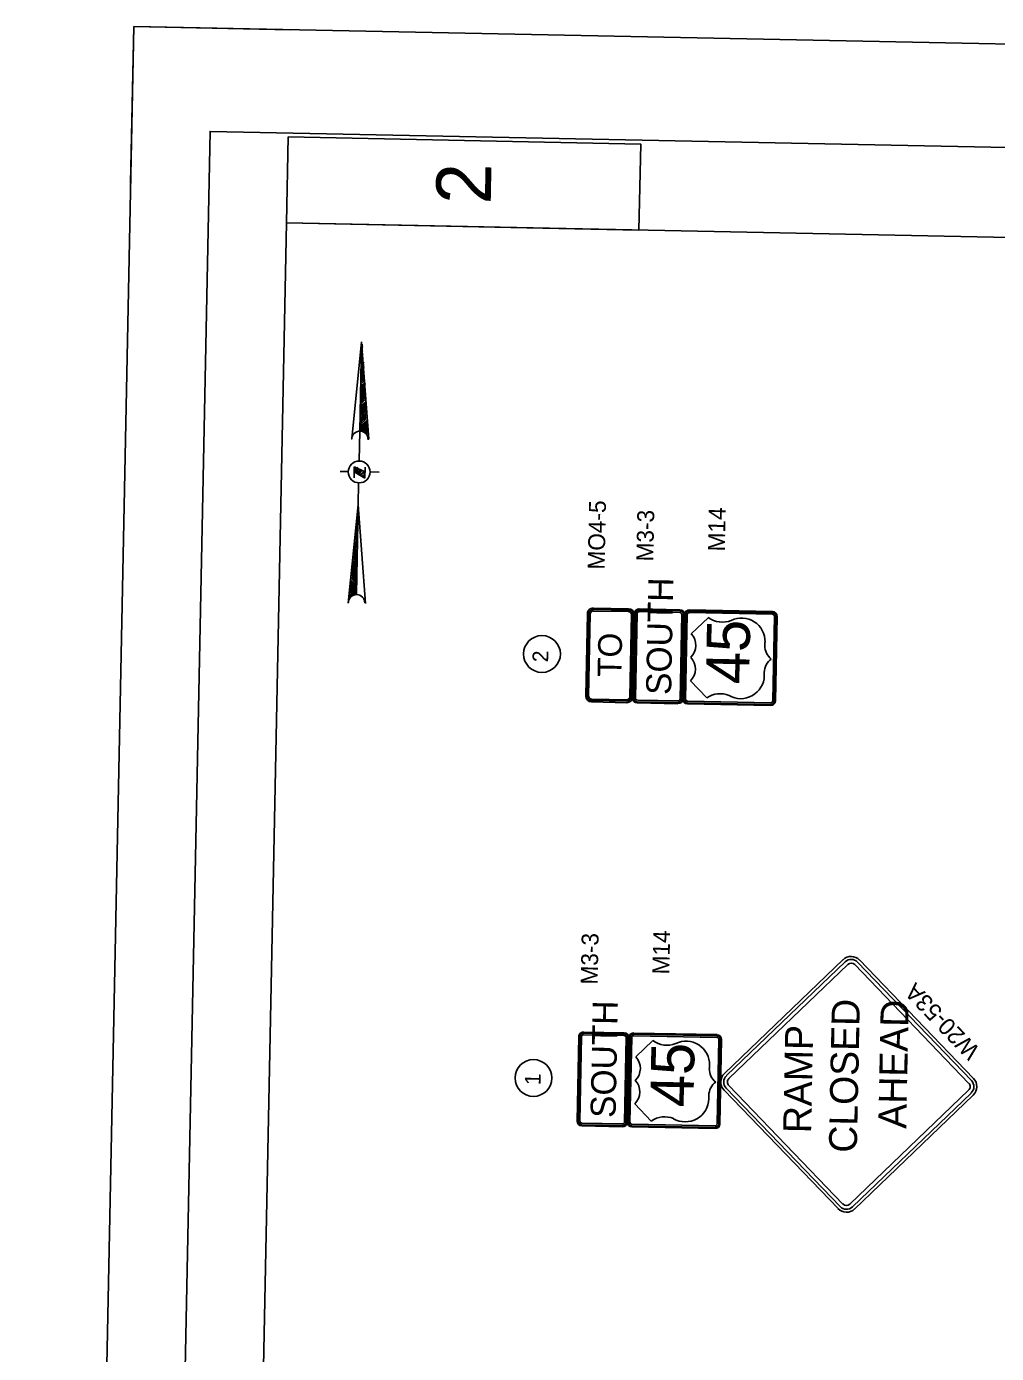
# Model space of a CAD drawing. Extents: x 327762 to 372975, y 127949 to 220470.
# Drawn here: x 344626 to 352364, y 209877 to 220470 of the extents above; entities that cross this region are included whole.
import ezdxf

# ---------------------------------------------------------------- set-up
doc = ezdxf.new("R2010")
doc.units = 0
for name, color, linetype in [('CA-TBLK', 7, 'Continuous'), ('CA-TEXT', 7, 'Continuous'), ('GSBWFILL', 7, 'Continuous'), ('P_SGN_Cell', 7, 'Continuous'), ('PLT_Sheet_Border', 7, 'Continuous'), ('PLT_Sheet_Info', 7, 'Continuous')]:
    doc.layers.add(name, color=color, linetype=linetype)

msp = doc.modelspace()

# ---------------------------------------------------------------- linework, layer by layer
at = {"layer": 'CA-TBLK'}
for p, q in [((347220, 217179), (347298, 217953)), ((347284, 217240), (347298, 217953)), ((347297, 217928), (347310, 217928)), ((347310, 217928), (347297, 217928)), ((347310, 217915), (347297, 217903)), ((347297, 217915), (347310, 217915)), ((347297, 217903), (347309, 217903)), ((347357, 217176), (347298, 217953)), ((347298, 217953), (347298, 217953)), ((347298, 217953), (347298, 217953)), ((347298, 217940), (347298, 217940)), ((347308, 217840), (347295, 217828)), ((347308, 217828), (347295, 217815)), ((347295, 217815), (347308, 217828)), ((347295, 217803), (347308, 217815)), ((347295, 217790), (347307, 217803)), ((347307, 217803), (347295, 217790)), ((347296, 217878), (347309, 217890)), ((347296, 217865), (347309, 217878)), ((347309, 217878), (347296, 217878)), ((347309, 217865), (347296, 217853)), ((347308, 217853), (347296, 217840)), ((347296, 217853), (347308, 217853)), ((347296, 217840), (347308, 217840)), ((347309, 217890), (347297, 217890)), ((347318, 217702), (347292, 217678)), ((347292, 217665), (347318, 217690)), ((347319, 217752), (347293, 217728)), ((347293, 217715), (347319, 217740)), ((347293, 217703), (347318, 217727)), ((347318, 217727), (347293, 217715)), ((347318, 217715), (347293, 217703)), ((347293, 217690), (347318, 217715)), ((347307, 217790), (347294, 217778)), ((347294, 217765), (347320, 217790)), ((347319, 217777), (347294, 217765)), ((347294, 217753), (347319, 217765)), ((347319, 217765), (347294, 217740)), ((347294, 217740), (347319, 217752)), ((347290, 217565), (347328, 217602)), ((347328, 217602), (347290, 217578)), ((347290, 217553), (347328, 217590)), ((347328, 217590), (347290, 217565)), ((347317, 217652), (347291, 217628)), ((347317, 217640), (347291, 217615)), ((347291, 217615), (347317, 217640)), ((347329, 217627), (347291, 217590)), ((347291, 217603), (347329, 217627)), ((347291, 217590), (347329, 217615)), ((347292, 217653), (347317, 217677)), ((347317, 217677), (347292, 217665)), ((347317, 217665), (347292, 217640)), ((347292, 217640), (347317, 217665)), ((347288, 217478), (347327, 217515)), ((347327, 217515), (347288, 217478)), ((347326, 217502), (347288, 217465)), ((347326, 217490), (347288, 217453)), ((347288, 217453), (347326, 217490)), ((347328, 217565), (347289, 217528)), ((347327, 217552), (347289, 217515)), ((347289, 217528), (347327, 217552)), ((347289, 217503), (347327, 217540)), ((347289, 217490), (347327, 217527)), ((347327, 217527), (347289, 217503)), ((347328, 217577), (347290, 217553)), ((347290, 217540), (347328, 217565)), ((347285, 217328), (347336, 217377)), ((347337, 217414), (347286, 217365)), ((347286, 217378), (347337, 217414)), ((347337, 217402), (347286, 217353)), ((347286, 217365), (347337, 217402)), ((347286, 217340), (347337, 217389)), ((347336, 217377), (347286, 217340)), ((347338, 217477), (347287, 217428)), ((347287, 217428), (347338, 217464)), ((347287, 217415), (347338, 217452)), ((347338, 217452), (347287, 217415)), ((347287, 217390), (347338, 217439)), ((347338, 217439), (347287, 217403)), ((347337, 217427), (347287, 217390)), ((347288, 217440), (347338, 217477)), ((347348, 217327), (347284, 217265)), ((347284, 217278), (347348, 217327)), ((347284, 217265), (347348, 217314)), ((347284, 217253), (347347, 217302)), ((347347, 217302), (347284, 217253)), ((347347, 217289), (347284, 217240)), ((347285, 217315), (347336, 217364)), ((347336, 217364), (347285, 217315)), ((347336, 217352), (347285, 217303)), ((347336, 217339), (347285, 217290)), ((347285, 217290), (347336, 217339)), ((347296, 217240), (347347, 217289)), ((347347, 217277), (347309, 217240)), ((347284, 217240), (347279, 217003)), ((347309, 217240), (347347, 217264)), ((347347, 217264), (347321, 217227)), ((347346, 217252), (347321, 217227)), ((347321, 217227), (347346, 217252)), ((347333, 217227), (347346, 217239)), ((347346, 217227), (347333, 217214)), ((347333, 217214), (347346, 217227)), ((347345, 217202), (347346, 217214)), ((347345, 217202), (347345, 217202)), ((347345, 217189), (347345, 217189)), ((347345, 217189), (347345, 217189)), ((347345, 217177), (347357, 217176)), ((347346, 217214), (347346, 217214)), ((347240, 216954), (347239, 216866)), ((347240, 216941), (347253, 216954)), ((347253, 216954), (347240, 216941)), ((347240, 216954), (347240, 216954)), ((347327, 216915), (347240, 216954)), ((347265, 216953), (347240, 216929)), ((347328, 216952), (347326, 216865)), ((347190, 216917), (347127, 216919)), ((347240, 216916), (347278, 216941)), ((347265, 216941), (347240, 216916)), ((347240, 216916), (347265, 216941)), ((347240, 216916), (347326, 216865)), ((347278, 216941), (347252, 216904)), ((347252, 216904), (347290, 216928)), ((347264, 216903), (347302, 216928)), ((347290, 216928), (347264, 216903)), ((347276, 216891), (347302, 216928)), ((347302, 216928), (347277, 216903)), ((347327, 216915), (347289, 216890)), ((347289, 216890), (347314, 216915)), ((347314, 216915), (347289, 216890)), ((347301, 216878), (347327, 216902)), ((347327, 216902), (347301, 216878)), ((347314, 216877), (347326, 216890)), ((347326, 216890), (347314, 216877)), ((347326, 216865), (347326, 216877)), ((347364, 216914), (347439, 216912)), ((347275, 216828), (347272, 216653)), ((347193, 215867), (347272, 216653)), ((347257, 215941), (347272, 216653)), ((347271, 216641), (347271, 216641)), ((347271, 216641), (347271, 216641)), ((347331, 215864), (347272, 216653)), ((347272, 216653), (347272, 216653)), ((347269, 216541), (347270, 216553)), ((347269, 216528), (347269, 216541)), ((347269, 216541), (347269, 216541)), ((347269, 216528), (347269, 216516)), ((347269, 216516), (347269, 216528)), ((347270, 216591), (347271, 216603)), ((347270, 216591), (347270, 216591)), ((347270, 216578), (347270, 216578)), ((347270, 216578), (347270, 216566)), ((347270, 216566), (347270, 216553)), ((347270, 216566), (347270, 216566)), ((347271, 216628), (347271, 216628)), ((347271, 216616), (347271, 216616)), ((347271, 216616), (347271, 216616)), ((347271, 216603), (347271, 216603)), ((347268, 216453), (347255, 216466)), ((347255, 216466), (347268, 216453)), ((347267, 216428), (347255, 216453)), ((347255, 216453), (347267, 216441)), ((347255, 216441), (347267, 216428)), ((347255, 216428), (347267, 216403)), ((347267, 216416), (347255, 216428)), ((347256, 216516), (347269, 216503)), ((347269, 216503), (347256, 216503)), ((347256, 216503), (347268, 216491)), ((347256, 216491), (347268, 216466)), ((347268, 216478), (347256, 216491)), ((347268, 216466), (347256, 216478)), ((347240, 216341), (347265, 216316)), ((347265, 216316), (347240, 216341)), ((347265, 216303), (347240, 216329)), ((347264, 216291), (347240, 216316)), ((347240, 216316), (347264, 216291)), ((347241, 216366), (347265, 216341)), ((347241, 216354), (347265, 216328)), ((347265, 216341), (347241, 216354)), ((347254, 216416), (347266, 216391)), ((347267, 216403), (347254, 216416)), ((347254, 216403), (347266, 216378)), ((347266, 216378), (347254, 216403)), ((347266, 216366), (347254, 216391)), ((347266, 216353), (347254, 216378)), ((347254, 216378), (347266, 216353)), ((347225, 216216), (347262, 216178)), ((347262, 216191), (347226, 216229)), ((347263, 216203), (347238, 216241)), ((347238, 216241), (347263, 216216)), ((347238, 216229), (347262, 216191)), ((347239, 216291), (347264, 216266)), ((347239, 216279), (347263, 216241)), ((347264, 216253), (347239, 216279)), ((347263, 216241), (347239, 216266)), ((347239, 216266), (347263, 216228)), ((347263, 216216), (347239, 216254)), ((347264, 216266), (347240, 216304)), ((347240, 216304), (347264, 216278)), ((347223, 216117), (347260, 216066)), ((347260, 216078), (347223, 216117)), ((347260, 216053), (347223, 216104)), ((347224, 216167), (347261, 216128)), ((347261, 216128), (347224, 216167)), ((347261, 216103), (347224, 216154)), ((347224, 216154), (347261, 216116)), ((347224, 216142), (347261, 216103)), ((347224, 216129), (347260, 216078)), ((347260, 216091), (347224, 216129)), ((347225, 216204), (347262, 216166)), ((347262, 216166), (347225, 216204)), ((347225, 216192), (347262, 216153)), ((347262, 216153), (347225, 216192)), ((347261, 216141), (347225, 216179)), ((347209, 216042), (347258, 215978)), ((347258, 215991), (347209, 216042)), ((347258, 215978), (347209, 216029)), ((347258, 215966), (347209, 216017)), ((347209, 216017), (347258, 215966)), ((347257, 215941), (347209, 216004)), ((347209, 216004), (347258, 215953)), ((347210, 216054), (347259, 216003)), ((347259, 216003), (347210, 216054)), ((347222, 216067), (347259, 216016)), ((347259, 216041), (347223, 216092)), ((347223, 216092), (347260, 216053)), ((347259, 216028), (347223, 216079)), ((347223, 216079), (347259, 216028)), ((347194, 215917), (347207, 215904)), ((347194, 215905), (347207, 215904)), ((347207, 215904), (347194, 215905)), ((347194, 215892), (347194, 215892)), ((347194, 215892), (347194, 215892)), ((347219, 215917), (347207, 215942)), ((347207, 215942), (347220, 215929)), ((347207, 215929), (347219, 215917)), ((347207, 215917), (347207, 215929)), ((347208, 215992), (347257, 215941)), ((347208, 215979), (347245, 215941)), ((347257, 215941), (347208, 215979)), ((347208, 215967), (347232, 215929)), ((347245, 215929), (347208, 215967)), ((347232, 215929), (347208, 215954)), ((347194, 215880), (347194, 215880))]:
    msp.add_line(p, q, dxfattribs=at)
msp.add_circle((347280, 216914), 87, dxfattribs=at)
for centre, start, end in [((347285, 217175), 358.8468, 178.8468), ((347285, 217175), 178.84682431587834, 178.8468298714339), ((347259, 215870), 358.8468, 178.8468), ((347259, 215870), 358.84700764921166, 358.8470132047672)]:
    msp.add_arc(centre, 65.2, start, end, dxfattribs=at)
at = {"layer": 'CA-TEXT'}
for centre in [(348738, 215461), (348670, 212076)]:
    msp.add_circle(centre, 147, dxfattribs=at)
at = {"layer": 'GSBWFILL'}
msp.add_lwpolyline([(344626, 177980), (345482, 220470), (372975, 219916), (372119, 177427)], close=True, dxfattribs=at)
at = {"layer": 'P_SGN_Cell'}
for p, q in [((349462, 215109), (349475, 215784)), ((349471, 215109), (349484, 215784)), ((349483, 215109), (349497, 215783)), ((349513, 215821), (349838, 215814)), ((349513, 215811), (349838, 215805)), ((349513, 215799), (349838, 215792)), ((349913, 215813), (350578, 215799)), ((349913, 215803), (350577, 215790)), ((349913, 215791), (350577, 215778)), ((349853, 215776), (349840, 215101)), ((349866, 215776), (349852, 215101)), ((349875, 215776), (349861, 215101)), ((349861, 215101), (349875, 215776)), ((349871, 215101), (349884, 215776)), ((349883, 215101), (349897, 215776)), ((349929, 215621), (350066, 215753)), ((350592, 215762), (350579, 215087)), ((350605, 215761), (350591, 215087)), ((350614, 215761), (350601, 215086)), ((350517, 215556), (350517, 215529)), ((350512, 215315), (350512, 215288)), ((349890, 215210), (349890, 215210)), ((350053, 215110), (349922, 215247)), ((349498, 215080), (349823, 215074)), ((349498, 215071), (349823, 215064)), ((349499, 215093), (349824, 215086)), ((349898, 215072), (350563, 215059)), ((349898, 215063), (350562, 215050)), ((349899, 215085), (350563, 215071)), ((349018, 211731), (349032, 212406)), ((349028, 211731), (349041, 212406)), ((349040, 211731), (349054, 212406)), ((349070, 212443), (349395, 212436)), ((349070, 212434), (349395, 212427)), ((349070, 212421), (349395, 212415)), ((349410, 212399), (349396, 211724)), ((349423, 212398), (349409, 211724)), ((349418, 211723), (349432, 212398)), ((349432, 212398), (349418, 211723)), ((349428, 211723), (349441, 212398)), ((349440, 211723), (349454, 212398)), ((349470, 212435), (350135, 212422)), ((349470, 212426), (350134, 212412)), ((349470, 212413), (350134, 212400)), ((349486, 212244), (349623, 212375)), ((350149, 212384), (350136, 211709)), ((350162, 212384), (350148, 211709)), ((350171, 212384), (350158, 211709)), ((350074, 212178), (350074, 212152)), ((349610, 211732), (349478, 211869)), ((350069, 211937), (350069, 211911)), ((349447, 211832), (349447, 211832)), ((349055, 211703), (349380, 211696)), ((349055, 211693), (349380, 211687)), ((349056, 211715), (349381, 211709)), ((349455, 211695), (350120, 211681)), ((349455, 211685), (350119, 211672)), ((349456, 211707), (350120, 211694))]:
    msp.add_line(p, q, dxfattribs=at)
for points in [[(349429, 215799), (349147, 215804)], [(349429, 215822), (349148, 215828)], [(349429, 215810), (349148, 215816)], [(349100, 215782), (349087, 215126)], [(349112, 215782), (349099, 215125)], [(349123, 215781), (349110, 215125)], [(349438, 215119), (349452, 215775)], [(349450, 215118), (349463, 215774)], [(349462, 215118), (349475, 215774)], [(349133, 215101), (349414, 215096)], [(349133, 215090), (349414, 215084)], [(349133, 215078), (349414, 215072)], [(351140, 213021), (350193, 212112)], [(351156, 213004), (350210, 212095)], [(351177, 212982), (350230, 212073)], [(352142, 212035), (351233, 212982)], [(352164, 212056), (351255, 213002)], [(352181, 212073), (351272, 213019)], [(350191, 211979), (351100, 211033)], [(350208, 211996), (351117, 211049)], [(350229, 212016), (351138, 211070)], [(351195, 211069), (352142, 211978)], [(351216, 211047), (352162, 211956)], [(351232, 211030), (352179, 211939)]]:
    msp.add_lwpolyline(points, dxfattribs=at)
for centre, radius, start, end in [((349147, 215781), 46.9, 88.8462, 178.8462), ((349147, 215781), 35.2, 88.8462, 178.8462), ((349147, 215781), 23.4, 88.8462, 178.8462), ((349428, 215775), 46.9, 358.8462, 88.8462), ((349428, 215775), 35.2, 358.8462, 88.8462), ((349428, 215775), 23.4, 358.8462, 88.8462), ((349513, 215783), 37.5, 88.8462, 178.8462), ((349513, 215783), 28.1, 88.8462, 178.8462), ((349513, 215783), 15.6, 88.8462, 178.8462), ((349838, 215777), 37.5, 358.8462, 88.8462), ((349838, 215777), 28.1, 358.8462, 88.8462), ((349838, 215777), 15.6, 358.8462, 88.8462), ((349913, 215775), 37.5, 88.8462, 178.8462), ((349913, 215775), 28.1, 88.8462, 178.8462), ((349913, 215775), 15.6, 88.8462, 178.8462), ((350577, 215762), 28.1, 358.8462, 88.8462), ((350577, 215762), 37.5, 358.8462, 88.8462), ((350178, 215903), 188, 233.1143, 291.9873), ((350330, 215560), 188, 358.8462, 115.6928), ((350577, 215762), 15.6, 358.8462, 88.8462), ((349832, 215530), 134, 314.4191, 43.2734), ((350652, 215527), 136, 179.1885, 231.634), ((349828, 215342), 134, 314.4191, 43.2734), ((350648, 215311), 136, 126.0584, 178.5039), ((350324, 215292), 188, 240.0981, 358.8463), ((349134, 215125), 46.9, 178.8462, 268.8462), ((349134, 215125), 35.2, 178.8462, 268.8462), ((349134, 215125), 23.4, 178.8462, 268.8462), ((349415, 215119), 23.4, 268.8462, 358.8462), ((349415, 215119), 46.9, 268.8462, 358.8462), ((349415, 215119), 35.2, 268.8462, 358.8462), ((349499, 215108), 37.5, 179.6119, 268.8462), ((349499, 215108), 28.1, 178.8462, 268.8462), ((349499, 215108), 15.6, 178.8462, 268.8462), ((349824, 215102), 28.1, 268.8462, 358.8462), ((349824, 215102), 37.5, 268.8462, 358.8462), ((349824, 215102), 15.6, 268.8462, 358.8462), ((349899, 215100), 37.5, 179.6119, 268.8462), ((349899, 215100), 28.1, 178.8462, 268.8462), ((349899, 215100), 15.6, 178.8462, 268.8462), ((350160, 214956), 188, 67.7159, 124.7982), ((350563, 215087), 37.5, 268.8462, 358.8462), ((350563, 215087), 28.1, 268.8462, 358.8462), ((350563, 215087), 15.6, 268.8462, 358.8462), ((351205, 212953), 93.7, 43.8462, 133.8462), ((351205, 212953), 69.9, 43.8462, 133.8462), ((351205, 212953), 40.2, 43.8462, 133.8462), ((349070, 212406), 37.5, 88.8462, 178.8462), ((349070, 212406), 28.1, 88.8462, 178.8462), ((349070, 212406), 15.6, 88.8462, 178.8462), ((349394, 212399), 37.5, 358.8462, 88.8462), ((349394, 212399), 28.1, 358.8462, 88.8462), ((349394, 212399), 15.6, 358.8462, 88.8462), ((349469, 212398), 37.5, 88.8462, 178.8462), ((349469, 212398), 28.1, 88.8462, 178.8462), ((349469, 212398), 15.6, 88.8462, 178.8462), ((350134, 212384), 28.1, 358.8462, 88.8462), ((350134, 212384), 15.6, 358.8462, 88.8462), ((350134, 212384), 37.5, 358.8462, 88.8462), ((349735, 212525), 188, 233.1143, 291.9873), ((349887, 212182), 188, 358.8462, 115.6928), ((349389, 212152), 134, 314.4191, 43.2734), ((350209, 212150), 136, 179.1885, 231.634), ((350258, 212044), 93.7, 133.8443, 223.8462), ((350258, 212044), 69.9, 133.8443, 223.8462), ((349385, 211965), 134, 314.4191, 43.2734), ((350205, 211934), 136, 126.0584, 178.5039), ((350258, 212044), 40.2, 133.8443, 223.8462), ((352114, 212007), 40.2, 313.8534, 44.4971), ((352114, 212007), 69.9, 313.8534, 44.4971), ((352114, 212007), 93.7, 313.8534, 44.4971), ((349881, 211914), 188, 240.0981, 358.8463), ((349717, 211578), 188, 67.7159, 124.7982), ((349056, 211731), 37.5, 179.6119, 268.8462), ((349056, 211731), 28.1, 178.8462, 268.8462), ((349056, 211731), 15.6, 178.8462, 268.8462), ((349381, 211724), 28.1, 268.8462, 358.8462), ((349381, 211724), 37.5, 268.8462, 358.8462), ((349381, 211724), 15.6, 268.8462, 358.8462), ((349456, 211723), 37.5, 179.6119, 268.8462), ((349456, 211723), 28.1, 178.8462, 268.8462), ((349456, 211723), 15.6, 178.8462, 268.8462), ((350120, 211709), 37.5, 268.8462, 358.8462), ((350120, 211709), 28.1, 268.8462, 358.8462), ((350120, 211709), 15.6, 268.8462, 358.8462), ((351167, 211098), 93.7, 223.8462, 313.8462), ((351167, 211098), 69.9, 223.8462, 313.8462), ((351167, 211098), 40.2, 223.8462, 313.8462)]:
    msp.add_arc(centre, radius, start, end, dxfattribs=at)
at = {"layer": 'PLT_Sheet_Border'}
for points in [[(372119, 177427), (372975, 219916), (345482, 220470), (344626, 177980)], [(371500, 177739), (372334, 219104), (346090, 219633), (345257, 178268)]]:
    msp.add_lwpolyline(points, close=True, dxfattribs=at)
at = {"layer": 'PLT_Sheet_Info'}
for p, q in [((345456, 219220), (345482, 220470)), ((346731, 220445), (345482, 220470)), ((345907, 179536), (346700, 218902)), ((371694, 218398), (346700, 218902))]:
    msp.add_line(p, q, dxfattribs=at)
msp.add_lwpolyline([(346700, 218902), (346714, 219589), (349526, 219532), (349512, 218845)], close=True, dxfattribs=at)

# ---------------------------------------------------------------- texts
at = {"layer": 'CA-TEXT'}
for s, p in [('2', (348787, 215394)), ('1', (348726, 212019))]:
    msp.add_text(s, height=125, rotation=88.8468, dxfattribs=at).set_placement(p)
at = {"layer": 'P_SGN_Cell'}
for s, height, rotation, p in [('MO4-5', 135, 88.8462, (349238, 216134)), ('M3-3', 135, 88.8462, (349626, 216199)), ('M14', 135, 88.8462, (350197, 216279)), ('SOUTH', 200, 88.8462, (349768, 215133)), ('45', 345, 88.8462, (350390, 215218)), ('TO', 190, 88.8462, (349371, 215276)), ('M14', 135, 88.8462, (349754, 212902)), ('M3-3', 135, 88.8462, (349182, 212821)), ('W20-53A', 135, 133.8468, (352240, 212302)), ('SOUTH', 200, 88.8462, (349325, 211756)), ('CLOSED', 223.2, 88.8462, (351250, 211478)), ('AHEAD', 223.2, 88.8462, (351644, 211670)), ('RAMP', 223.2, 88.8462, (350885, 211634)), ('45', 345, 88.8462, (349946, 211841))]:
    msp.add_text(s, height=height, rotation=rotation, dxfattribs=at).set_placement(p)
at = {"layer": 'PLT_Sheet_Info'}
msp.add_text('2', height=437, rotation=88.8462, dxfattribs=at).set_placement((348329, 219049))

doc.saveas('drawing.dxf')
